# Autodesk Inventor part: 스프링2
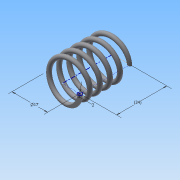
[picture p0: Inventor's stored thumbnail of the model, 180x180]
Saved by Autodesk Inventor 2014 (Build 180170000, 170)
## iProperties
Created: 2016-01
Part Number: 스프링2
Material: 강철, 탄소
Document SubType Name: Modeling
Designer: Administrator
Density: 1 g/cm^3
Appearance: 반연마
Mass: 0.818602 g
Surface Area: 16.6857 cm^2
Volume: 0.818602 cm^3
Author: Administrator
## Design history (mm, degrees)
sketch "스케치1"
  geometry: L1 (0, 0)-(8.5, 0); L2 (8.5, 0)-(8.5, 17.5); L3 (8.5, 17.5)-(0, 17.5); L4 (0, 17.5)-(0, 0); C1 r 1 at (8.5, 0)
  constraints: 8 end point, 2 parallel, 1 centre point, 1 coincident, 1 horizontal, 1 perpendicular
  dimensions: "d0" = 17.5 distance of L1.end L2.end (derived); "d1" = 17 diameter of L2 L4; "d2" = 2 diameter of C1
feature "코일1" sketch "스케치1" pitch "d3" = 10; turns "d5" = 5; dims "d4" = 17.5 (= d0), "d6" = 0, angle "d7" = 90 deg, angle "d8" = 90 deg, "d9" = 0, "d10" = 0
node "작업 평면2"
  node "작업 평면1"
sketch "스케치2"
  geometry: L1 (-9.5, 0)-(-7.5, 0) reference; 1 further point
  constraints: 1 horizontal alignment
extrude "돌출1" cut sketch "스케치2" distance "d13" = 10; taper "d14" = 0 deg
sketch "스케치3"
  geometry: L1 (-7.5, 0)-(-9.5, 0) reference; 1 further point
  constraints: 1 horizontal alignment
extrude "돌출2" cut sketch "스케치3" distance "d15" = 10; taper "d16" = 0 deg
node "솔리드1"
node "절단 모서리 투영1"
node "절단 모서리 투영2"
other parameters: "d11" = 0, "d12" = 17.5 (= d0)
